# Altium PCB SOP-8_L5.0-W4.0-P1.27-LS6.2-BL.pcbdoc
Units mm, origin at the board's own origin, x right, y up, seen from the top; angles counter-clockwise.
Board outline 18.19 x 20.46 mm, 2 copper layers (Top Layer, Bottom Layer), stack 0 mm thick; 1 components, 0 nets, 8 pads, 0 vias.
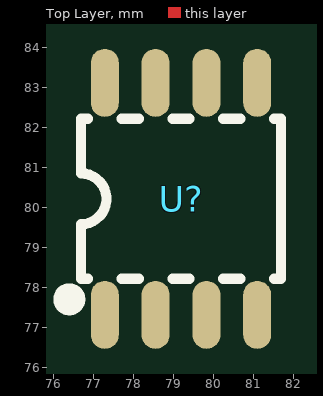
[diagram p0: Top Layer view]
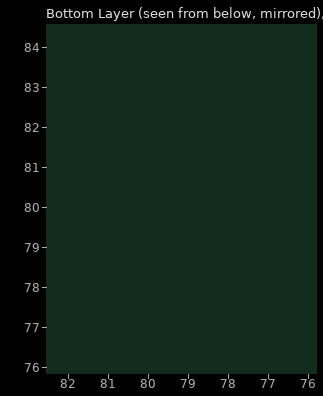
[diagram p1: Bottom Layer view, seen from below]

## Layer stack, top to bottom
Top Layer: signal copper (thickness not stored)
Bottom Layer: signal copper (thickness not stored)

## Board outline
88.043,69.85 69.85,69.85 69.85,90.31 88.043,90.31

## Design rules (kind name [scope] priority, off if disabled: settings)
PasteMaskExpansion "Paste Mask Expansion" [All] p1: expansion=0
SolderMaskExpansion "Solder Mask Expansion" [IsVia] p1: expansion=-25.4 istentingtop=TRUE
SolderMaskExpansion "Solder Mask Expansion" [All] p2: expansion=0.051 istentingtop=FALSE

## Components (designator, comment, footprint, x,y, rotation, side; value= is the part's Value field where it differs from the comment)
U? "" SOP-8_L5.0-W4.0-P1.27-LS6.2-BL 79.193,80.21 r0 top

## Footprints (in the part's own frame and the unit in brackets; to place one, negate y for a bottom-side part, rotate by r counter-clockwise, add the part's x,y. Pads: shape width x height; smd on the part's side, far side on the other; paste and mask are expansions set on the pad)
SOP-8_L5.0-W4.0-P1.27-LS6.2-BL [mm]
  oval 0.7x1.7 smd: 1(-1.905,-2.9) 2(-0.635,-2.9) 3(0.635,-2.9) 4(1.905,-2.9) 5(1.905,2.9) 6(0.635,2.9) 7(-0.635,2.9) 8(-1.905,2.9)
  silkscreen extent -2.99,-2.71 2.5,2

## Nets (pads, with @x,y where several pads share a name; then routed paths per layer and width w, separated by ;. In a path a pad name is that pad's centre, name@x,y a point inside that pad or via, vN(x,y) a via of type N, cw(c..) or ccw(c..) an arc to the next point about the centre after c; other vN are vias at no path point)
pads on no net: U?.1 U?.2 U?.3 U?.4 U?.5 U?.6 U?.7 U?.8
